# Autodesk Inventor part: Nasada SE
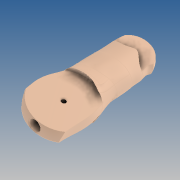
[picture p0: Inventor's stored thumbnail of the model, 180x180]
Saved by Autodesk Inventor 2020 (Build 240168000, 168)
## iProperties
Created: 2019-10
Part Number: Nasada SE
Material: GFRP
Document SubType Name: Modeling
Designer: yello
Density: 1.75 g/cm^3
Appearance: Default
Author: yello
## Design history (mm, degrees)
node "Annotations"
  node "Leader Text 1"
feature "Nasada SE"
workplane "Work Plane1"
sketch "Sketch1"
  geometry: L1 (3.426, -0.717)-(7.524, 18.858); L2 (7.524, 18.858)-(0.672, 20.293); L3 (0.672, 20.293)-(-3.426, 0.717); L4 (-3.426, 0.717)-(-9.573, -28.646); L5 (-9.573, -28.646)-(-2.722, -30.081); L6 (-2.722, -30.081)-(3.426, -0.717); L7 (-6.147, -29.363)-(4.098, 19.576); A1 r 3.5 centre (0, 0) between (3.426, -0.717) and (-3.426, 0.717)
  constraints: 14 end point, 3 perpendicular, 2 midpoint, 2 point on circle, 2 point on line, 2 tangent, 1 centre point
  dimensions: "d0" = 7 diameter of A1; "d1" = 20 distance of L1.start L1.end; "d2" = 30 distance of L3.end L4.end
revolve "Revolution1" sketch "Sketch1" stored, may be unused: angle "d3" = 90 deg
workplane "Work Plane2"
workplane "Work Plane3"
workplane "Work Plane4"
sketch "Sketch2" dims "d8" = 3
  geometry: L1 (-2.722, -30.081)-(-9.573, -28.646); L2 (-6.147, -29.363)-(0, 0); L3 (0, 0)-(0.307, 1.468); 2 further points
  constraints: 6 end point, 1 coincident, 1 midpoint, 3 other
  dimensions: "d7" = 30 distance of L2.start L2.end
revolve "Revolution2" sketch "Sketch2" stored, may be unused: angle "d9" = 90 deg
mirror "Mirror1"
workplane "Work Plane5"
sketch "Sketch6"
  geometry: L1 (-0.147, 13.857)-(-0.093, 6.857) reference; L2 (-0.12, 10.357)-(3.63, 10.386); L3 (3.63, 10.386)-(11.879, 10.449); L4 (3.637, 9.386)-(11.887, 9.449); L5 (11.872, 11.449)-(3.622, 11.386); A1 r 1 centre (3.63, 10.386) between (3.622, 11.386) and (3.637, 9.386); A2 r 1 centre (11.879, 10.449) between (11.887, 9.449) and (11.872, 11.449); 2 further points
  constraints: 10 end point, 4 point on circle, 4 tangent, 2 centre point, 2 midpoint, 2 parallel, 1 perpendicular
  dimensions: "d22" = 3.75 distance of L2.start L2.end; "d23" = 8.25 distance of L2.end L3.end; "d24" = 2 diameter of A2
extrude "Extrusion3" cut sketch "Sketch6" distance "d25" = 14; taper "d26" = 0 deg
body "Solid1"
other parameters: "d4" = 0, "d6" = -0.5, "d15" = 7.42011 (derived), "d16" = 6.081 (derived)
